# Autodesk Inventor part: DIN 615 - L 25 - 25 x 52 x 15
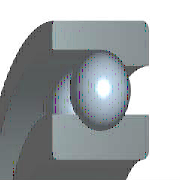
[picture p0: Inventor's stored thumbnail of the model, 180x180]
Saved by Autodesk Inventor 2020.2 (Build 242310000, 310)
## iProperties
Manager: www.cadconsulting.pl
Company: Fabian Stasiak CAD Consulting
Created: 2014-02
Part Number: DIN 615 - L 25 - 25 x 52 x 15
Material: Stal, miękka
Description: Łożysko kulkowe
Document SubType Name: Modeling
Standard: DIN 615
Designer: F.Stasiak
Standards Organization: DIN
Language: pl-PL
Size Designation: L 25 - 25 x 52 x 15
Categories: <MemberInstance><Categories><Category DisplayName="Części wałów" InternalName="7f7aeb1f-a693-4053-b835-cee3144e0d98" Mnemonic="SHFT"><Category DisplayName="Łoży
Density: 7.85 g/cm^3
Appearance: Częściowo polerowana
Catalog Web Link: www.expertbooks.pl
IsCustomPart: 0
Author: F.Stasiak
Subject: Zbiór ćwiczeń. Autodesk Inventor 2020. Kurs Professional
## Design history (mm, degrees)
sketch "Szkic" dims "d4" = 7.83 (= DDB)
  geometry: L1 (3.585, 19.25)-(11.415, 19.25); L2 (4.368, 16.901)-(0, 16.901); L3 (10.632, 16.901)-(15, 16.901); L4 (7.5, 23.165)-(0, 23.165); L5 (0, 26)-(15, 26); L6 (0, 12.5)-(15, 12.5); L7 (15, 12.5)-(15, 16.901); L8 (10.632, 21.599)-(15, 21.599); L9 (15, 21.599)-(15, 26); L10 (7.5, 19.25)-(7.5, 23.165); L11 (7.5, 19.25)-(7.5, 15.335); L12 (-3.2, 0)-(19.2, 0) reference; L13 (0, -2.6)-(0, 17.35) reference
  constraints: 22 end point, 5 parallel, 4 collinear, 4 point on line, 2 perpendicular, 1 horizontal, 1 midpoint, 9 other
  dimensions: "d10" = 25 diameter of L6 L12 (= WD); "d12" = 43.198 diameter of L8 L12 (= KAD1); "d14" = 38.5 diameter of L10.start L12 (= DDA); "d15" = 52 diameter of L5 L12 (= BD); "d16" = 33.802 diameter of L2 L12 (= KID1); "d17" = 15 distance between parallel lines of L13 L7 (= KB); "d18" = 7.5 distance from line of L13 L10.start (= 0.5 x KB)
revolve "Bryła" stored, may be unused: angle "d8" = 90 deg
revolve "Łożysko kulkowe" stored, may be unused: angle "d11" = 90 deg
pattern_circular "Kulki" dims angle "d3" = 360 deg
body "Solid1"
fillet "Zaokrąglenie1" dims "d0" = 1 (= KR1S), "d1" = 0.6 (= KR3S)
other parameters: "WD" = 25 [user parameter; used in 2 equation terms], "BD" = 52 [user parameter; used in 2 equation terms], "KB" = 15 [user parameter; used in 2 equation terms], "KR1S" = 1 [user parameter; used in 1 equation term], "KR3S" = 0.6 [user parameter; used in 1 equation term], "KID1" = 33.802 [user parameter; used in 1 equation term], "KAD1" = 43.198 [user parameter; used in 2 equation terms], "DDA" = 38.5 [user parameter; used in 1 equation term], "DDB" = 7.83 [user parameter; used in 2 equation terms], "d5" = 0, "d6" = 0, "d7" = 0, "d9" = 0, "d19" = 0, "WR" = 12.5 (= 0.5 x WD) [user parameter], "BC" = 8650000 [user parameter], "BC0" = 1730000 [user parameter], "DBB" = 46.33 [user parameter], "BR" = 26 (= 0.5 x BD) [user parameter], "BBA" = 0 [user parameter]
